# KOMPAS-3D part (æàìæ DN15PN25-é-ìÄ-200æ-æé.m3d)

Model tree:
1. Объединить компоненты:1  (labels: СЕНС DN15PN25-В-НО-200С)
2. Эскиз:1
3. Операция выдавливания:1
     Расстояние 1 = 14
4. Фаска:1
     Угол = 45; Длина 1 = 2; Длина 2 = 2

Referenced files in D:\Савин\!СЕНСОР\3D для заказчика\!Новый перечень\СЕНС\7. СЕНС-В-НО-200С\DN15\: СЕНС DN15PN25-В-НО-200С.a3d
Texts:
  СЕНС DN15PN25-В-НО-200С-СВ
  ООО НПП Сенсор
  СЕНС DN15PN25-В-НО-200С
